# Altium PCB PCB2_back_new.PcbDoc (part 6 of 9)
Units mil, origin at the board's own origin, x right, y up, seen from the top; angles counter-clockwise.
Board outline 6299 x 3937 mil, 4 copper layers (TopLayer, GROUND, VCC, BottomLayer); 253 components, 421 nets, 2085 pads, 712 vias.
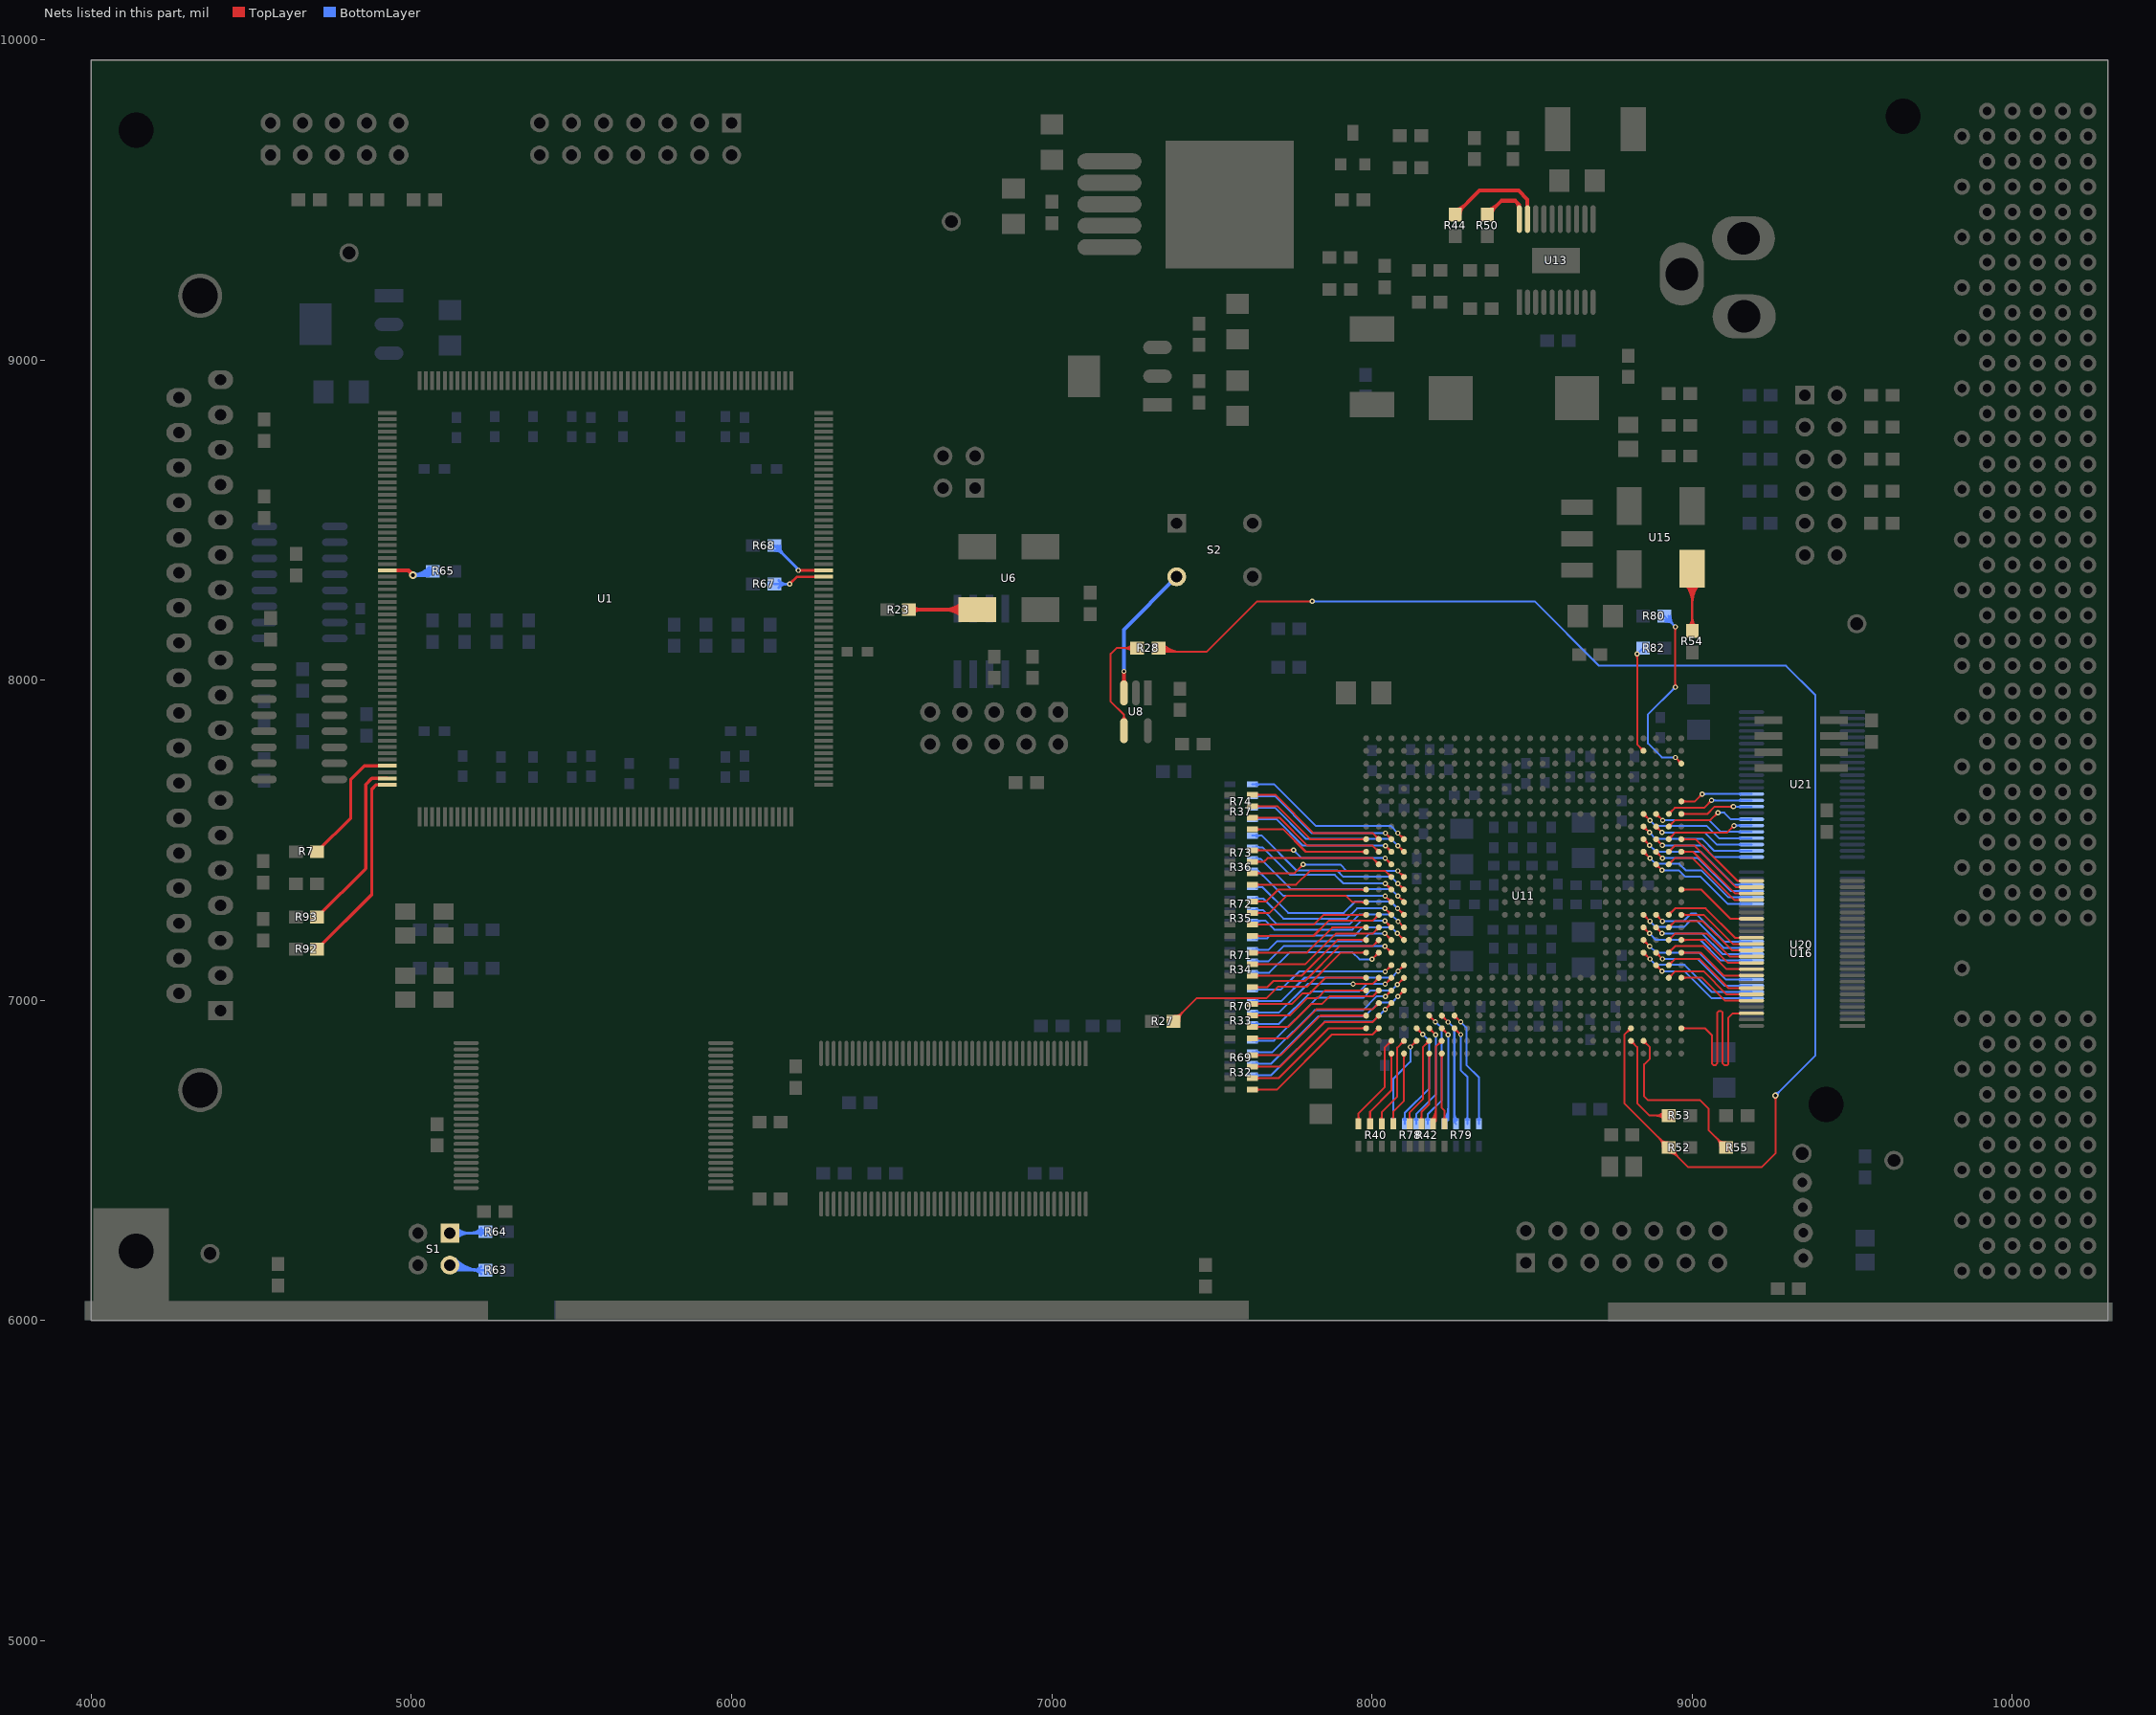
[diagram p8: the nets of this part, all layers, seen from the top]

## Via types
v1: diameter 16, hole 8, TopLayer to BottomLayer, 311 vias
v2: diameter 20, hole 10, TopLayer to BottomLayer, 202 vias
v3: diameter 24, hole 12, TopLayer to BottomLayer, 179 vias
v4: diameter 40, hole 20, TopLayer to BottomLayer, 12 vias
v5: diameter 30, hole 15, TopLayer to BottomLayer, 8 vias

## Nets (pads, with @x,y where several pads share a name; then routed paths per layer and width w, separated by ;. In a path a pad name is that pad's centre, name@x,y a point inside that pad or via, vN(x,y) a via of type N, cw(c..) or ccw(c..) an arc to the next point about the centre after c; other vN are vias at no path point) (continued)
NetR7_2: R7.2 U1.177 | length 401.7
  TopLayer w10: R7.2@4705.46,7464 4810.3,7568.84 4810.3,7690.3 4852.35,7732.35 U1.177@4924.9,7732.35
NetR23_1: R23.1 U6.3 | length 473.2
  TopLayer w12: R23.1@6553.46,8220 U6.3@6767.15,8220 ; R23.1@6565.11,8210.32 cw(c6588.47,8186.96) 6588.47,8220 cw(c6588.47,8253.04) R23.1@6565.11,8229.68 ; U6.3@6723.87,8196.4 ccw(c6666.9,8139.44) 6666.9,8220 ccw(c6666.9,8300.56) U6.3@6723.87,8243.6 ; U6.3@6732.35,8204.89 ccw(c6695.87,8168.41) 6695.87,8220 ccw(c6695.87,8271.59) U6.3@6732.35,8235.11
NetR27_1: R27.1 U11.J26 | length 818.8
  TopLayer w6: R27.1@7379.46,6934 7452.46,7007 7671,7007 7706,7042 7796,7042 7902.96,7148.96 U11.J26@7981.75,7148.96 ; R27.1@7381.43,6944.69 ccw(c7381.43,6965.73) R27.1@7396.31,6950.85 ; R27.1@7381.43,6950.69 ccw(c7381.43,6986.21) 7406.56,6961.09 ; R27.1@7392.12,6934 cw(c7422.67,6934) 7401.07,6955.6 ; R27.1@7398.12,6934 cw(c7443.15,6934) 7411.31,6965.84 ; U11.J26@7977.33,7144.54 ccw(c7966.65,7133.87) 7966.65,7148.96 ccw(c7966.65,7164.05) U11.J26@7977.33,7153.38
NetR28_1: R28.1 U8.4 | length 484.4
  TopLayer w6: U8.4@7218.97,7875.68 ccw(c7203.93,7890.72) 7225.2,7890.72 ccw(c7246.47,7890.72) U8.4@7231.43,7875.68 ; U8.4@7225.2,7841.89 7225.2,7891.8 7184,7933 7184,8082 7202,8100 R28.1@7266.54,8100 ; R28.1@7252.77,8088.2 ccw(c7224.29,8059.72) 7224.29,8100 ccw(c7224.29,8140.28) R28.1@7252.77,8111.8 ; R28.1@7257.01,8092.44 ccw(c7238.77,8074.2) 7238.77,8100 ccw(c7238.77,8125.8) R28.1@7257.01,8107.56
NetR28_2: R28.2 R52.2 U11.C5 | length 5030.8
  TopLayer w6: R28.2@7333.46,8100 7345.46,8088 7483,8088 7641,8246 v1(7813,8246) ; R28.2@7334.5,8099.07 ccw(c7361.23,8125.8) 7361.23,8088 ; R28.2@7338.75,8103.31 ccw(c7375.71,8140.28) 7375.71,8088 ; R28.2@7342.99,8107.56 ccw(c7390.2,8154.77) 7390.2,8088 ; R28.2@7347.23,8111.8 ccw(c7404.68,8169.25) 7404.68,8088 ; U11.C5@8802.27,6912.74 cw(c8787.17,6912.74) 8797.85,6902.07 cw(c8808.52,6891.39) U11.C5@8808.52,6906.49 ; U11.C5@8808.52,6912.74 8788,6892.22 8788,6678.54 8987.54,6479 9217,6479 9260,6522 v2(9260,6703) ; 8894.69,6571.84 cw(c8862.85,6540) R52.2@8907.88,6540 ; 8899.44,6567.09 ccw(c8924.57,6592.21) R52.2@8924.57,6556.69 ; 8904.93,6561.6 cw(c8883.33,6540) R52.2@8913.88,6540 ; R52.2@8909.69,6556.85 ccw(c8924.57,6571.73) R52.2@8924.57,6550.69 ; R52.2@8928.5,6523.31 cw(c8928.5,6487.79) 8953.63,6512.91 ; R52.2@8928.5,6529.31 cw(c8928.5,6508.27) R52.2@8943.38,6523.15 ; R52.2@8939.19,6540 ccw(c8969.74,6540) 8948.14,6518.4 ; R52.2@8945.19,6540 ccw(c8990.22,6540) 8958.38,6508.16 ; v2@9255.05,6698.05 cw(c9243.1,6686.1) 9260,6686.1 cw(c9276.9,6686.1) v2@9264.95,6698.05
  BottomLayer w6: v1(7813,8246) 8508,8246 8709,8045 9293,8045 9384,7954 9384,6827 v2(9260,6703) ; v1@7816.54,8242.46 cw(c7825.07,8233.93) 7825.07,8246 cw(c7825.07,8258.07) v1@7816.54,8249.54 ; v2@9260,6710 ccw(c9260,6726.9) 9271.95,6714.95 ccw(c9283.9,6703) v2@9267,6703
NetR32_1: R32.1 U11.C25 | length 521
  TopLayer w6: R32.1@7626,6721 7703,6721 7875,6893 8001.38,6893 U11.C25@8021.12,6912.74 ; R32.1@7638.74,6716.76 cw(c7648.99,6706.51) 7648.99,6721 cw(c7648.99,6735.49) R32.1@7638.74,6725.24 ; U11.C25@8014.87,6912.74 cw(c7999.77,6912.74) 8010.44,6902.07 cw(c8021.12,6891.39) U11.C25@8021.12,6906.49
NetR32_2: R32.2 U11.C26 | length 470.6
  TopLayer w6: R32.2@7628.74,6759.74 R32.2@7626,6757 7709,6757 7864.74,6912.74 U11.C26@7981.75,6912.74 ; R32.2@7638.74,6752.76 cw(c7648.99,6742.51) 7648.99,6757 cw(c7648.99,6771.49) R32.2@7638.74,6761.24 ; U11.C26@7977.33,6908.32 ccw(c7966.65,6897.65) 7966.65,6912.74 ccw(c7966.65,6927.83) U11.C26@7977.33,6917.16
NetR32_3: R32.3 U11.D25 | length 507.5
  TopLayer w6: R32.3@7626,6793 7713,6793 7852,6932 8001.01,6932 U11.D25@8021.12,6952.11 ; R32.3@7638.74,6788.76 cw(c7648.99,6778.51) 7648.99,6793 cw(c7648.99,6807.49) R32.3@7638.74,6797.24 ; U11.D25@8014.87,6952.11 cw(c7999.77,6952.11) 8010.44,6941.44 cw(c8021.12,6930.77) U11.D25@8021.12,6945.86
NetR32_4: R32.4 U11.D26 | length 453.2
  TopLayer w6: R32.4@7626,6829 7716,6829 7839.11,6952.11 U11.D26@7981.75,6952.11 ; R32.4@7638.74,6824.76 cw(c7648.99,6814.51) 7648.99,6829 cw(c7648.99,6843.49) R32.4@7638.74,6833.24 ; U11.D26@7977.33,6947.69 ccw(c7966.65,6937.02) 7966.65,6952.11 ccw(c7966.65,6967.2) U11.D26@7977.33,6956.53
NetR33_1: R33.1 U11.E25 | length 487.3
  TopLayer w6: R33.1@7626,6881 7735,6881 7826,6972 8001.64,6972 U11.E25@8021.12,6991.48 ; R33.1@7638.74,6876.76 cw(c7648.99,6866.51) 7648.99,6881 cw(c7648.99,6895.49) R33.1@7638.74,6885.24 ; U11.E25@8014.87,6991.48 cw(c7999.77,6991.48) 8010.44,6980.81 cw(c8021.12,6970.14) U11.E25@8021.12,6985.23
NetR33_2: R33.2 U11.F25 | length 488.7
  TopLayer w6: R33.2@7626,6917 7739,6917 7811,6989 7844,6989 7867,7012 8002.27,7012 U11.F25@8021.12,7030.85 ; R33.2@7638.74,6912.76 cw(c7648.99,6902.51) 7648.99,6917 cw(c7648.99,6931.49) R33.2@7638.74,6921.24 ; U11.F25@8014.87,7030.85 cw(c7999.77,7030.85) 8010.44,7020.18 cw(c8021.12,7009.51) U11.F25@8021.12,7024.6
NetR33_3: R33.3 U11.F26 | length 434.5
  TopLayer w6: R33.3@7626,6953 7744.15,6953 7797.15,7006 7829,7006 7853.85,7030.85 U11.F26@7981.75,7030.85 ; R33.3@7638.74,6948.76 cw(c7648.99,6938.51) 7648.99,6953 cw(c7648.99,6967.49) R33.3@7638.74,6957.24 ; U11.F26@7977.33,7026.43 ccw(c7966.65,7015.76) 7966.65,7030.85 ccw(c7966.65,7045.94) U11.F26@7977.33,7035.27
NetR33_4: R33.4 U11.G26 | length 435.9
  TopLayer w6: R33.4@7626,6989 7750,6989 7782,7021 7805,7021 7854.22,7070.22 U11.G26@7981.75,7070.22 ; R33.4@7638.74,6984.76 cw(c7648.99,6974.51) 7648.99,6989 cw(c7648.99,7003.49) R33.4@7638.74,6993.24 ; U11.G26@7977.33,7065.8 ccw(c7966.65,7055.13) 7966.65,7070.22 ccw(c7966.65,7085.31) U11.G26@7977.33,7074.64
NetR34_1: R34.1 U11.K25 | length 502.6
  TopLayer w6: R34.1@7626,7041 7673,7041 7692.45,7060.45 7790.45,7060.45 7899,7169 8001.79,7169 U11.K25@8021.12,7188.33 ; R34.1@7638.74,7036.76 cw(c7648.99,7026.51) 7648.99,7041 cw(c7648.99,7055.49) R34.1@7638.74,7045.24 ; U11.K25@8014.87,7188.33 cw(c7999.77,7188.33) 8010.44,7177.66 cw(c8021.12,7166.99) U11.K25@8021.12,7182.08
NetR34_2: R34.2 U11.K26 | length 448.3
  TopLayer w6: R34.2@7626,7077 7781,7077 7892.33,7188.33 U11.K26@7981.75,7188.33 ; R34.2@7638.74,7072.76 cw(c7648.99,7062.51) 7648.99,7077 cw(c7648.99,7091.49) R34.2@7638.74,7081.24 ; U11.K26@7977.33,7183.91 ccw(c7966.65,7173.24) 7966.65,7188.33 ccw(c7966.65,7203.42) U11.K26@7977.33,7192.75
NetR34_3: R34.3 U11.L25 | length 489.1
  TopLayer w6: R34.3@7626,7113 7792,7113 7887,7208 8001.42,7208 U11.L25@8021.12,7227.7 ; R34.3@7638.74,7108.76 cw(c7648.99,7098.51) 7648.99,7113 cw(c7648.99,7127.49) R34.3@7638.74,7117.24 ; U11.L25@8014.87,7227.7 cw(c7999.77,7227.7) 8010.44,7217.03 cw(c8021.12,7206.36) U11.L25@8021.12,7221.45
NetR34_4: R34.4 U11.L26 | length 434.8
  TopLayer w6: R34.4@7626,7149 7797,7149 7875.7,7227.7 U11.L26@7981.75,7227.7 ; R34.4@7638.74,7144.76 cw(c7648.99,7134.51) 7648.99,7149 cw(c7648.99,7163.49) R34.4@7638.74,7153.24 ; U11.L26@7977.33,7223.28 ccw(c7966.65,7212.61) 7966.65,7227.7 ccw(c7966.65,7242.79) U11.L26@7977.33,7232.12
NetR35_1: R35.1 U11.M25 | length 468.9
  TopLayer w6: R35.1@7626,7201 7817,7201 7864,7248 8002.05,7248 U11.M25@8021.12,7267.07 ; R35.1@7638.74,7196.76 cw(c7648.99,7186.51) 7648.99,7201 cw(c7648.99,7215.49) R35.1@7638.74,7205.24 ; U11.M25@8014.87,7267.07 cw(c7999.77,7267.07) 8010.44,7256.4 cw(c8021.12,7245.73) U11.M25@8021.12,7260.82
NetR35_2: R35.2 U11.M26 | length 414.7
  TopLayer w6: R35.2@7626,7237 7819,7237 7849.07,7267.07 U11.M26@7981.75,7267.07 ; R35.2@7638.74,7232.76 cw(c7648.99,7222.51) 7648.99,7237 cw(c7648.99,7251.49) R35.2@7638.74,7241.24 ; U11.M26@7977.33,7262.65 ccw(c7966.65,7251.98) 7966.65,7267.07 ccw(c7966.65,7282.16) U11.M26@7977.33,7271.49
NetR35_3: R35.3 U11.N26 | length 432.3
  TopLayer w6: R35.3@7626,7273 7680,7273 7733,7326 7919,7326 7938.56,7306.44 U11.N26@7981.75,7306.44 ; R35.3@7638.74,7268.76 cw(c7648.99,7258.51) 7648.99,7273 cw(c7648.99,7287.49) R35.3@7638.74,7277.24 ; U11.N26@7977.33,7302.02 ccw(c7966.65,7291.35) 7966.65,7306.44 ccw(c7966.65,7321.53) U11.N26@7977.33,7310.86
NetR35_4: R35.4 U11.P26 | length 417.5
  TopLayer w6: R35.4@7626,7309 7670,7309 7706.81,7345.81 U11.P26@7981.75,7345.81 ; R35.4@7638.74,7304.76 cw(c7648.99,7294.51) 7648.99,7309 cw(c7648.99,7323.49) R35.4@7638.74,7313.24 ; U11.P26@7977.33,7341.39 ccw(c7966.65,7330.72) 7966.65,7345.81 ccw(c7966.65,7360.9) U11.P26@7977.33,7350.23
NetR36_1: R36.1 U11.R24 | length 506.6
  TopLayer w6: R36.1@7626,7361 7763,7361 7806,7404 8041.67,7404 U11.R24@8060.49,7385.18 ; R36.1@7638.74,7356.76 cw(c7648.99,7346.51) 7648.99,7361 cw(c7648.99,7375.49) R36.1@7638.74,7365.24 ; U11.R24@8054.24,7385.18 ccw(c8039.14,7385.18) 8049.82,7395.85 ccw(c8060.49,7406.53) U11.R24@8060.49,7391.43
NetR36_2: R36.2 U11.R23 | length 585.5
  TopLayer w6: R36.2@7626,7397 7758,7397 v1(7785,7424) ; R36.2@7638.74,7392.76 cw(c7648.99,7382.51) 7648.99,7397 cw(c7648.99,7411.49) R36.2@7638.74,7401.24 ; v1@7780,7424 cw(c7767.93,7424) 7776.46,7415.46 cw(c7785,7406.93) v1@7785,7419 ; v1(8081.04,7404) U11.R23@8099.86,7385.18 ; U11.R23@8093.61,7385.18 ccw(c8078.51,7385.18) 8089.19,7395.85 ccw(c8099.86,7406.53) U11.R23@8099.86,7391.43
  BottomLayer w6: v1(7785,7424) 7901,7424 7921,7404 v1(8081.04,7404) ; v1@7788.54,7420.46 cw(c7797.07,7411.93) 7797.07,7424 cw(c7797.07,7436.07) v1@7788.54,7427.54
NetR36_3: R36.3 U11.T25 | length 454.2
  TopLayer w6: R36.3@7626,7433 7663,7433 7674,7444 8001.67,7444 U11.T25@8021.12,7424.55 ; R36.3@7638.74,7428.76 cw(c7648.99,7418.51) 7648.99,7433 cw(c7648.99,7447.49) R36.3@7638.74,7437.24 ; U11.T25@8014.87,7424.55 ccw(c7999.77,7424.55) 8010.44,7435.22 ccw(c8021.12,7445.9) U11.T25@8021.12,7430.8
NetR36_4: R36.4 U11.T24 | length 537.3
  TopLayer w6: R36.4@7626,7469 v1(7755,7469) ; R36.4@7638.74,7464.76 cw(c7648.99,7454.51) 7648.99,7469 cw(c7648.99,7483.49) R36.4@7638.74,7473.24 ; v1@7751.46,7465.46 ccw(c7742.93,7456.93) 7742.93,7469 ccw(c7742.93,7481.07) v1@7751.46,7472.54 ; v1(8041.04,7444) U11.T24@8060.49,7424.55 ; U11.T24@8054.24,7424.55 ccw(c8039.14,7424.55) 8049.82,7435.22 ccw(c8060.49,7445.9) U11.T24@8060.49,7430.8
  BottomLayer w6: v1@7755,7464 cw(c7755,7451.93) 7763.54,7460.46 cw(c7772.07,7469) v1@7760,7469 ; v1(7755,7469) 7780,7444 v1(8041.04,7444)
NetR37_1: R37.1 U11.U26 | length 431.2
  TopLayer w6: R37.1@7626,7534 7723,7534 7793.08,7463.92 U11.U26@7981.75,7463.92 ; R37.1@7638.74,7529.76 cw(c7648.99,7519.51) 7648.99,7534 cw(c7648.99,7548.49) R37.1@7638.74,7538.24 ; U11.U26@7977.33,7459.5 ccw(c7966.65,7448.83) 7966.65,7463.92 ccw(c7966.65,7479.02) U11.U26@7977.33,7468.34
NetR37_2: R37.2 U11.U25 | length 485.5
  TopLayer w6: R37.2@7626,7570 7711,7570 7798,7483 8002.04,7483 U11.U25@8021.12,7463.92 ; R37.2@7638.74,7565.76 cw(c7648.99,7555.51) 7648.99,7570 cw(c7648.99,7584.49) R37.2@7638.74,7574.24 ; U11.U25@8014.87,7463.92 ccw(c7999.77,7463.92) 8010.44,7474.59 ccw(c8021.12,7485.27) U11.U25@8021.12,7470.17
NetR37_3: R37.3 U11.V26 | length 444.8
  TopLayer w6: R37.3@7626,7606 7704,7606 7806.71,7503.29 U11.V26@7981.75,7503.29 ; R37.3@7638.74,7601.76 cw(c7648.99,7591.51) 7648.99,7606 cw(c7648.99,7620.49) R37.3@7638.74,7610.24 ; U11.V26@7977.33,7498.87 ccw(c7966.65,7488.2) 7966.65,7503.29 ccw(c7966.65,7518.39) U11.V26@7977.33,7507.71
NetR37_4: R37.4 U11.V25 | length 499
  TopLayer w6: R37.4@7626,7642 7698,7642 7818,7522 8002.41,7522 U11.V25@8021.12,7503.29 ; R37.4@7638.74,7637.76 cw(c7648.99,7627.51) 7648.99,7642 cw(c7648.99,7656.49) R37.4@7638.74,7646.24 ; U11.V25@8014.87,7503.29 ccw(c7999.77,7503.29) 8010.44,7513.96 ccw(c8021.12,7524.64) U11.V25@8021.12,7509.54
NetR40_1: R40.1 U11.A23 | length 280.5
  TopLayer w6: R40.1@8061.76,6626.74 ccw(c8051.51,6636.99) 8066,6636.99 ccw(c8080.49,6636.99) R40.1@8070.24,6626.74 ; R40.1@8066,6614 8066,6652 8099.86,6685.86 U11.A23@8099.86,6834 ; U11.A23@8095.44,6829.58 cw(c8084.76,6818.91) 8099.86,6818.91 cw(c8114.95,6818.91) U11.A23@8104.28,6829.58
NetR40_2: R40.2 U11.B23 | length 334.8
  TopLayer w6: R40.2@8025.76,6626.74 ccw(c8015.51,6636.99) 8030,6636.99 ccw(c8044.49,6636.99) R40.2@8034.24,6626.74 ; R40.2@8030,6614 8030,6650 8079,6699 8079,6852.51 U11.B23@8099.86,6873.37 ; U11.B23@8093.61,6873.37 cw(c8078.51,6873.37) 8089.19,6862.7 cw(c8099.86,6852.02) U11.B23@8099.86,6867.12
NetR40_3: R40.3 U11.A24 | length 294
  TopLayer w6: R40.3@7989.76,6626.74 ccw(c7979.51,6636.99) 7994,6636.99 ccw(c8008.49,6636.99) R40.3@7998.24,6626.74 ; R40.3@7994,6614 7994,6652 8060.49,6718.49 U11.A24@8060.49,6834 ; U11.A24@8056.07,6829.58 cw(c8045.39,6818.91) 8060.49,6818.91 cw(c8075.58,6818.91) U11.A24@8064.91,6829.58
NetR40_4: R40.4 U11.B24 | length 348.3
  TopLayer w6: R40.4@7953.76,6626.74 ccw(c7943.51,6636.99) 7958,6636.99 ccw(c7972.49,6636.99) R40.4@7962.24,6626.74 ; R40.4@7958,6614 7958,6647 8040,6729 8040,6852.88 U11.B24@8060.49,6873.37 ; U11.B24@8054.24,6873.37 cw(c8039.14,6873.37) 8049.82,6862.7 cw(c8060.49,6852.02) U11.B24@8060.49,6867.12
NetR42_1: R42.1 U11.A20 | length 269.8
  TopLayer w6: U11.A20@8213.55,6829.58 cw(c8202.87,6818.91) 8217.97,6818.91 cw(c8233.06,6818.91) U11.A20@8222.39,6829.58 ; U11.A20@8217.97,6834 8217.97,6664.03 8226,6656 R42.1@8226,6614 ; R42.1@8221.76,6626.74 ccw(c8211.51,6636.99) 8226,6636.99 ccw(c8240.49,6636.99) R42.1@8230.24,6626.74
NetR42_2: R42.2 U11.B20 | length 367.1
  TopLayer w6: R42.2@8185.76,6626.74 ccw(c8153.79,6658.71) 8199,6658.71 ; R42.2@8190,6614 8199,6623 8199,6854.4 U11.B20@8217.97,6873.37 ; R42.2@8190,6622.5 ccw(c8168.27,6644.23) 8199,6644.23 ; R42.2@8194.24,6618.26 ccw(c8182.76,6629.74) 8199,6629.74 ; U11.B20@8211.72,6873.37 cw(c8196.62,6873.37) 8207.3,6862.7 cw(c8217.97,6852.02) U11.B20@8217.97,6867.12
NetR42_3: R42.3 U11.A21 | length 276.7
  TopLayer w6: R42.3@8149.76,6626.74 ccw(c8139.51,6636.99) 8154,6636.99 ccw(c8168.49,6636.99) R42.3@8158.24,6626.74 ; R42.3@8154,6614 8154,6651 8178.6,6675.6 U11.A21@8178.6,6834 ; U11.A21@8174.18,6829.58 cw(c8163.5,6818.91) 8178.6,6818.91 cw(c8193.69,6818.91) U11.A21@8183.02,6829.58
NetR42_4: R42.4 U11.B21 | length 330.9
  TopLayer w6: R42.4@8113.76,6626.74 ccw(c8103.51,6636.99) 8118,6636.99 ccw(c8132.49,6636.99) R42.4@8122.24,6626.74 ; R42.4@8118,6614 8118,6650 8159,6691 8159,6853.77 U11.B21@8178.6,6873.37 ; U11.B21@8172.35,6873.37 cw(c8157.25,6873.37) 8167.93,6862.7 cw(c8178.6,6852.02) U11.B21@8178.6,6867.12
NetR44_1: R44.1 U13.19 | length 381.8
  TopLayer w12: R44.1@8260,9453.46 8335.54,9529 8458,9529 8485.59,9501.41 U13.19@8485.59,9439.84 ; R44.1@8260,9469.12 ccw(c8260,9506.91) 8286.72,9480.19 ; R44.1@8273.69,9455.43 cw(c8301.97,9455.43) 8281.97,9475.43
NetR50_2: R50.2 U13.20 | length 239.6
  TopLayer w12: R50.2@8360,9453.46 8403.54,9497 8447,9497 8460,9484 U13.20@8460,9439.84 ; R50.2@8360,9469.12 ccw(c8360,9506.91) 8386.72,9480.19 ; R50.2@8373.69,9455.43 cw(c8401.97,9455.43) 8381.97,9475.43 ; 8450.63,9493.37 cw(c8432.54,9475.28) U13.20@8458.13,9475.28
NetR53_2: R53.2 U11.B5 | length 448.1
  TopLayer w6: U11.B5@8808.52,6867.12 cw(c8808.52,6852.02) 8819.19,6862.7 cw(c8829.86,6873.37) U11.B5@8814.77,6873.37 ; U11.B5@8808.52,6873.37 8828,6853.89 8828,6679 8867,6640 R53.2@8926.54,6640 R53.2@8926.54,6643.46 ; R53.2@8912.77,6628.2 ccw(c8884.29,6599.72) 8884.29,6640 ccw(c8884.29,6680.28) R53.2@8912.77,6651.8 ; R53.2@8917.01,6632.44 ccw(c8898.77,6614.2) 8898.77,6640 ccw(c8898.77,6665.8) R53.2@8917.01,6647.56
NetR54_1: R54.1 U15.3 | length 584.5
  TopLayer w8: U15.3@8974.99,8302.45 cw(c8914.61,8242.07) 9000,8242.07 cw(c9085.39,8242.07) U15.3@9025.01,8302.45 ; U15.3@8980.65,8308.11 cw(c8933.92,8261.39) 9000,8261.39 cw(c9066.08,8261.39) U15.3@9019.35,8308.11 ; U15.3@8986.3,8313.77 cw(c8953.24,8280.7) 9000,8280.7 cw(c9046.76,8280.7) U15.3@9013.7,8313.77 ; R54.1@8988.91,8166.52 ccw(c8962.13,8193.3) 9000,8193.3 ccw(c9037.87,8193.3) R54.1@9011.09,8166.52 ; R54.1@9000,8153.46 U15.3@9000,8367.15
NetR55_2: R55.2 U11.B4 | length 678.4
  TopLayer w6: U11.B4@8847.89,6867.12 cw(c8847.89,6852.02) 8858.56,6862.7 cw(c8869.24,6873.37) U11.B4@8854.14,6873.37 ; U11.B4@8847.89,6873.37 8868,6853.26 8868,6818 8850,6800 8850,6700 8862,6688 9025,6688 9051,6662 9051,6595.54 R55.2@9106.54,6540 ; 9074.69,6571.84 cw(c9042.85,6540) R55.2@9087.88,6540 ; 9079.44,6567.09 ccw(c9104.57,6592.21) R55.2@9104.57,6556.69 ; 9084.93,6561.6 cw(c9063.33,6540) R55.2@9093.88,6540 ; R55.2@9089.69,6556.85 ccw(c9104.57,6571.73) R55.2@9104.57,6550.69
NetR63_2: R63.2 S1.2 | length 452.9
  BottomLayer w8: S1.2@5118,6173 5134,6157 R63.2@5230.54,6157 ; S1.2@5121.08,6174.08 ccw(c5162.32,6215.32) 5162.32,6157 ; S1.2@5126.74,6179.74 ccw(c5181.63,6234.63) 5181.63,6157 ; S1.2@5132.39,6185.39 ccw(c5200.94,6253.94) 5200.94,6157 ; S1.2@5138.05,6191.05 ccw(c5220.26,6273.26) R63.2@5220.26,6157 ; R63.2@5217.48,6145.91 ccw(c5190.7,6119.13) 5190.7,6157 ccw(c5190.7,6194.87) R63.2@5217.48,6168.09
NetR64_2: R64.2 S1.1 | length 362.2
  BottomLayer w8: S1.1@5118,6273 5226.54,6273 R64.2@5230.54,6277 ; S1.1@5132.39,6260.61 cw(c5162.32,6230.68) 5162.32,6273 cw(c5162.32,6315.32) S1.1@5132.39,6285.39 ; S1.1@5138.05,6254.95 cw(c5181.63,6211.37) 5181.63,6273 cw(c5181.63,6334.63) S1.1@5138.05,6291.05 ; 5181.04,6273 ccw(c5181.04,6324.52) R64.2@5217.48,6288.09 ; R64.2@5217.48,6265.91 ccw(c5200.36,6248.79) 5200.36,6273 ccw(c5200.36,6305.21) R64.2@5223.13,6282.43
NetR67_2: R67.2 U1.34 | length 240.1
  TopLayer w8: v1(6181,8300) 6203.9,8322.9 U1.34@6274.31,8322.9 ; v1@6181,8304 ccw(c6181,8313.66) 6187.83,8306.83 ccw(c6194.66,8300) v1@6185,8300
  BottomLayer w8: R67.2@6133.46,8300 v1(6181,8300) ; R67.2@6146.52,8288.91 cw(c6173.3,8262.13) 6173.3,8300 cw(c6173.3,8337.87) R67.2@6146.52,8311.09 ; v1@6178.17,8297.17 ccw(c6171.34,8290.34) 6171.34,8300 ccw(c6171.34,8309.66) v1@6178.17,8302.83
NetR68_2: R68.2 U1.35 | length 282.8
  TopLayer w8: v1(6208.58,8342.58) U1.35@6274.31,8342.58 ; v1@6211.41,8339.75 cw(c6218.24,8332.93) 6218.24,8342.58 cw(c6218.24,8352.24) v1@6211.41,8345.41
  BottomLayer w8: R68.2@6133.46,8420 6208.58,8344.88 v1(6208.58,8342.58) v1@6206,8340 ; R68.2@6135.43,8404.32 cw(c6135.43,8371.2) 6158.85,8394.62 ; R68.2@6143.12,8420 ccw(c6166.42,8420) R68.2@6149.94,8403.52 ; R68.2@6151.12,8420 ccw(c6193.74,8420) 6163.6,8389.86 ; 6200.13,8353.34 cw(c6189.37,8342.58) v1@6204.58,8342.58
NetR69_1: R69.1 U11.G23 | length 601.8
  TopLayer w6: v1(8079,7049) 8099.86,7069.86 U11.G23@8099.86,7070.22 ; 8088.93,7058.93 ccw(c8077.64,7070.22) U11.G23@8093.61,7070.22 ; 8089.8,7059.8 cw(c8099.86,7049.75) U11.G23@8099.86,7063.97
  BottomLayer w6: R69.1@7626,6874 7694,6874 7828,7008 7973,7008 7996,7031 8061,7031 v1(8079,7049) ; R69.1@7638.74,6869.76 cw(c7648.99,6859.51) 7648.99,6874 cw(c7648.99,6888.49) R69.1@7638.74,6878.24
NetR69_2: R69.2 U11.F24 | length 560.8
  TopLayer w6: v1(8041.64,7012) U11.F24@8060.49,7030.85 ; U11.F24@8054.24,7030.85 cw(c8039.14,7030.85) 8049.82,7020.18 cw(c8060.49,7009.51) U11.F24@8060.49,7024.6
  BottomLayer w6: R69.2@7626,6838 7689,6838 7820,6969 7971,6969 8014,7012 v1(8041.64,7012) ; R69.2@7638.74,6833.76 cw(c7648.99,6823.51) 7648.99,6838 cw(c7648.99,6852.49) R69.2@7638.74,6842.24
NetR69_3: R69.3 U11.F23 | length 615.1
  TopLayer w6: v1(8081.01,7012) U11.F23@8099.86,7030.85 ; U11.F23@8093.61,7030.85 cw(c8078.51,7030.85) 8089.19,7020.18 cw(c8099.86,7009.51) U11.F23@8099.86,7024.6
  BottomLayer w6: R69.3@7626,6802 7685,6802 7833,6950 7978,6950 8021,6993 8062.01,6993 v1(8081.01,7012) ; R69.3@7638.74,6797.76 cw(c7648.99,6787.51) 7648.99,6802 cw(c7648.99,6816.49) R69.3@7638.74,6806.24
NetR69_4: R69.4 U11.E24 | length 574.3
  TopLayer w6: v1(8041.01,6972) U11.E24@8060.49,6991.48 ; U11.E24@8054.24,6991.48 cw(c8039.14,6991.48) 8049.82,6980.81 cw(c8060.49,6970.14) U11.E24@8060.49,6985.23
  BottomLayer w6: R69.4@7626,6766 7685,6766 7852,6933 8002.01,6933 v1(8041.01,6972) ; R69.4@7638.74,6761.76 cw(c7648.99,6751.51) 7648.99,6766 cw(c7648.99,6780.49) R69.4@7638.74,6770.24
NetR70_1: R70.1 U11.H24 | length 512.3
  TopLayer w6: v1(8040.9,7090) U11.H24@8060.49,7109.59 ; U11.H24@8054.24,7109.59 cw(c8039.14,7109.59) 8049.82,7098.92 cw(c8060.49,7088.25) U11.H24@8060.49,7103.34
  BottomLayer w6: R70.1@7626,7034 7716,7034 7772,7090 v1(8040.9,7090) ; R70.1@7638.74,7029.76 cw(c7648.99,7019.51) 7648.99,7034 cw(c7648.99,7048.49) R70.1@7638.74,7038.24
NetR70_2: R70.2 U11.H23 | length 566.5
  TopLayer w6: v1(8081.27,7091) U11.H23@8099.86,7109.59 ; U11.H23@8093.61,7109.59 cw(c8078.51,7109.59) 8089.19,7098.92 cw(c8099.86,7088.25) U11.H23@8099.86,7103.34
  BottomLayer w6: R70.2@7626,6998 7717,6998 7790,7071 8061.27,7071 v1(8081.27,7091) ; R70.2@7638.74,6993.76 cw(c7648.99,6983.51) 7648.99,6998 cw(c7648.99,7012.49) R70.2@7638.74,7002.24
NetR70_3: R70.3 U11.G25 | length 486.4
  TopLayer w6: v1(7941,7051) 8001.9,7051 U11.G25@8021.12,7070.22 ; U11.G25@8014.87,7070.22 cw(c7999.77,7070.22) 8010.44,7059.55 cw(c8021.12,7048.88) U11.G25@8021.12,7063.97
  BottomLayer w6: R70.3@7626,6962 7710,6962 7799,7051 v1(7941,7051) ; R70.3@7638.74,6957.76 cw(c7648.99,6947.51) 7648.99,6962 cw(c7648.99,6976.49) R70.3@7638.74,6966.24
NetR70_4: R70.4 U11.G24 | length 540.7
  TopLayer w6: v1(8041.27,7051) U11.G24@8060.49,7070.22 ; U11.G24@8054.24,7070.22 cw(c8039.14,7070.22) 8049.82,7059.55 cw(c8060.49,7048.88) U11.G24@8060.49,7063.97
  BottomLayer w6: R70.4@7626,6926 7709,6926 7810,7027 7960,7027 7984,7051 v1(8041.27,7051) ; R70.4@7638.74,6921.76 cw(c7648.99,6911.51) 7648.99,6926 cw(c7648.99,6940.49) R70.4@7638.74,6930.24
NetR71_1: R71.1 U11.K23 | length 550.8
  TopLayer w6: v1(8079.19,7209) U11.K23@8099.86,7188.33 ; U11.K23@8093.61,7188.33 ccw(c8078.51,7188.33) 8089.19,7199 ccw(c8099.86,7209.68) U11.K23@8099.86,7194.58
  BottomLayer w6: R71.1@7626,7194 7673,7194 7682,7203 7947,7203 7972,7228 8060.19,7228 v1(8079.19,7209) ; R71.1@7638.74,7189.76 cw(c7648.99,7179.51) 7648.99,7194 cw(c7648.99,7208.49) R71.1@7638.74,7198.24
NetR71_2: R71.2 U11.K24 | length 510.6
  TopLayer w6: v1(8039.82,7209) U11.K24@8060.49,7188.33 ; U11.K24@8054.24,7188.33 ccw(c8039.14,7188.33) 8049.82,7199 ccw(c8060.49,7209.68) U11.K24@8060.49,7194.58
  BottomLayer w6: R71.2@7626,7158 7677,7158 7704,7185 7968,7185 7992,7209 v1(8039.82,7209) ; R71.2@7638.74,7153.76 cw(c7648.99,7143.51) 7648.99,7158 cw(c7648.99,7172.49) R71.2@7638.74,7162.24
NetR71_3: R71.3 U11.J24 | length 508.7
  TopLayer w6: v1(8040.45,7169) U11.J24@8060.49,7148.96 ; U11.J24@8054.24,7148.96 ccw(c8039.14,7148.96) 8049.82,7159.63 ccw(c8060.49,7170.31) U11.J24@8060.49,7155.21
  BottomLayer w6: R71.3@7626,7122 7677,7122 7724,7169 v1(8040.45,7169) ; R71.3@7638.74,7117.76 cw(c7648.99,7107.51) 7648.99,7122 cw(c7648.99,7136.49) R71.3@7638.74,7126.24
NetR71_4: R71.4 U11.J25 | length 485.9
  TopLayer w6: v1(8000.16,7128) U11.J25@8021.12,7148.96 ; U11.J25@8014.87,7148.96 cw(c7999.77,7148.96) 8010.44,7138.29 cw(c8021.12,7127.62) U11.J25@8021.12,7142.71
  BottomLayer w6: R71.4@7626,7086 7679,7086 7743,7150 7939,7150 7961,7128 v1(8000.16,7128) ; R71.4@7638.74,7081.76 cw(c7648.99,7071.51) 7648.99,7086 cw(c7648.99,7100.49) R71.4@7638.74,7090.24
NetR72_1: R72.1 U11.M23 | length 577.5
  TopLayer w6: v1(8079.93,7287) U11.M23@8099.86,7267.07 ; U11.M23@8093.61,7267.07 ccw(c8078.51,7267.07) 8089.19,7277.74 ccw(c8099.86,7288.42) U11.M23@8099.86,7273.32
  BottomLayer w6: R72.1@7638.74,7349.76 cw(c7648.99,7339.51) 7648.99,7354 cw(c7648.99,7368.49) R72.1@7638.74,7358.24 ; R72.1@7639.92,7351.42 cw(c7644,7349.48) 7644,7354 ; R72.1@7639.92,7356.58 ccw(c7644,7358.52) 7644,7354 ; v1(8079.93,7287) 8058.93,7308 7947,7308 7912,7273 7738,7273 7657,7354 7644,7354
NetR72_2: R72.2 U11.M24 | length 528.6
  TopLayer w6: v1(8040.56,7287) U11.M24@8060.49,7267.07 ; U11.M24@8054.24,7267.07 ccw(c8039.14,7267.07) 8049.82,7277.74 ccw(c8060.49,7288.42) U11.M24@8060.49,7273.32
  BottomLayer w6: R72.2@7626,7318 7660,7318 7723,7255 7921,7255 7953,7287 v1(8040.56,7287) ; R72.2@7638.74,7313.76 cw(c7648.99,7303.51) 7648.99,7318 cw(c7648.99,7332.49) R72.2@7638.74,7322.24
NetR72_3: R72.3 U11.L23 | length 544
  TopLayer w6: v1(8081.56,7246) U11.L23@8099.86,7227.7
  BottomLayer w6: R72.3@7626,7282 7659,7282 7703,7238 7930,7238 7960,7268 8059.56,7268 v1(8081.56,7246) ; R72.3@7638.74,7277.76 cw(c7648.99,7267.51) 7648.99,7282 cw(c7648.99,7296.49) R72.3@7638.74,7286.24
NetR72_4: R72.4 U11.L24 | length 512.6
  TopLayer w6: v1(8040.19,7248) U11.L24@8060.49,7227.7 ; U11.L24@8054.24,7227.7 ccw(c8039.14,7227.7) 8049.82,7238.37 ccw(c8060.49,7249.05) U11.L24@8060.49,7233.95
  BottomLayer w6: R72.4@7626,7246 7628,7248 7668,7248 7695,7221 7939,7221 7966,7248 v1(8040.19,7248) ; R72.4@7638.74,7241.76 cw(c7653.81,7226.69) 7653.81,7248 ; R72.4@7638.74,7250.24 ccw(c7644.16,7255.66) 7644.16,7248
NetR73_1: R73.1 U11.P23 | length 590
  TopLayer w6: v1(8080.67,7365) U11.P23@8099.86,7345.81 ; U11.P23@8093.61,7345.81 ccw(c8078.51,7345.81) 8089.19,7356.48 ccw(c8099.86,7367.16) U11.P23@8099.86,7352.06
  BottomLayer w6: R73.1@7626,7514 7656,7514 7764.29,7405.71 7890.29,7405.71 7910,7386 8059.67,7386 v1(8080.67,7365) ; R73.1@7638.74,7509.76 cw(c7648.99,7499.51) 7648.99,7514 cw(c7648.99,7528.49) R73.1@7638.74,7518.24
NetR73_2: R73.2 U11.P24 | length 535.7
  TopLayer w6: v1(8041.3,7365) U11.P24@8060.49,7345.81 ; U11.P24@8054.24,7345.81 ccw(c8039.14,7345.81) 8049.82,7356.48 ccw(c8060.49,7367.16) U11.P24@8060.49,7352.06
  BottomLayer w6: R73.2@7626,7478 7658,7478 7743.96,7392.04 7883.96,7392.04 7911,7365 v1(8041.3,7365) ; R73.2@7638.74,7473.76 cw(c7648.99,7463.51) 7648.99,7478 cw(c7648.99,7492.49) R73.2@7638.74,7482.24
NetR73_3: R73.3 U11.N23 | length 563.7
  TopLayer w6: v1(8081,7326) 8099.86,7307.14 U11.N23@8099.86,7306.44 ; 8090.38,7316.62 ccw(c8099.86,7326.09) U11.N23@8099.86,7312.69
  BottomLayer w6: R73.3@7626,7442 7652,7442 7747,7347 8060,7347 v1(8081,7326) ; R73.3@7638.74,7437.76 cw(c7648.99,7427.51) 7648.99,7442 cw(c7648.99,7456.49) R73.3@7638.74,7446.24
NetR73_4: R73.4 U11.N24 | length 543
  TopLayer w6: v1(8040.93,7326) U11.N24@8060.49,7306.44 ; U11.N24@8054.24,7306.44 ccw(c8039.14,7306.44) 8049.82,7317.11 ccw(c8060.49,7327.79) U11.N24@8060.49,7312.69
  BottomLayer w6: R73.4@7626,7406 7643,7406 7723,7326 v1(8040.93,7326) ; R73.4@7634.5,7400 cw(c7634.5,7364.99) 7659.25,7389.75 ; R73.4@7634.5,7406 cw(c7634.5,7385.48) 7649.01,7399.99
NetR74_1: R74.1 U11.V23 | length 591
  TopLayer w6: v1(8081.15,7522) U11.V23@8099.86,7503.29 ; U11.V23@8093.61,7503.29 ccw(c8078.51,7503.29) 8089.19,7513.96 ccw(c8099.86,7524.64) U11.V23@8099.86,7509.54
  BottomLayer w6: R74.1@7626,7674 7695,7674 7825,7544 8059.15,7544 v1(8081.15,7522) ; R74.1@7638.74,7669.76 cw(c7648.99,7659.51) 7648.99,7674 cw(c7648.99,7688.49) R74.1@7638.74,7678.24
NetR74_2: R74.2 U11.V24 | length 519.7
  TopLayer w6: v1(8041.78,7522) U11.V24@8060.49,7503.29 ; U11.V24@8054.24,7503.29 ccw(c8039.14,7503.29) 8049.82,7513.96 ccw(c8060.49,7524.64) U11.V24@8060.49,7509.54
  BottomLayer w6: R74.2@7638.74,7633.76 cw(c7648.99,7623.51) 7648.99,7638 cw(c7648.99,7652.49) R74.2@7638.74,7642.24 ; R74.2@7643,7638 7696,7638 7812,7522 v1(8041.78,7522)
NetR74_3: R74.3 U11.U23 | length 577.5
  TopLayer w6: v1(8080.78,7483) U11.U23@8099.86,7463.92 ; U11.U23@8093.61,7463.92 ccw(c8078.51,7463.92) 8089.19,7474.59 ccw(c8099.86,7485.27) U11.U23@8099.86,7470.17
  BottomLayer w6: R74.3@7626,7602 7696,7602 7793,7505 8058.78,7505 v1(8080.78,7483) ; R74.3@7638.74,7597.76 cw(c7648.99,7587.51) 7648.99,7602 cw(c7648.99,7616.49) R74.3@7638.74,7606.24
NetR74_4: R74.4 U11.U24 | length 523.2
  TopLayer w6: v1(8041.41,7483) U11.U24@8060.49,7463.92 ; U11.U24@8054.24,7463.92 ccw(c8039.14,7463.92) 8049.82,7474.59 ccw(c8060.49,7485.27) U11.U24@8060.49,7470.17
  BottomLayer w6: R74.4@7626,7566 7701,7566 7784,7483 v1(8041.41,7483) ; R74.4@7638.74,7561.76 cw(c7648.99,7551.51) 7648.99,7566 cw(c7648.99,7580.49) R74.4@7638.74,7570.24
NetR78_1: R78.1 U11.B22 | length 336.2
  TopLayer w6: v1(8120,6854.14) U11.B22@8139.23,6873.37 ; U11.B22@8132.98,6873.37 cw(c8117.88,6873.37) 8128.56,6862.7 cw(c8139.23,6852.02) U11.B22@8139.23,6867.12
  BottomLayer w6: R78.1@8061.76,6626.74 ccw(c8051.51,6636.99) 8066,6636.99 ccw(c8080.49,6636.99) R78.1@8070.24,6626.74 ; R78.1@8066,6614 8066,6754 8120,6808 v1(8120,6854.14)
NetR78_2: R78.2 U11.C22 | length 393.6
  TopLayer w6: U11.C22@8139.23,6906.49 cw(c8139.23,6891.39) 8149.9,6902.07 cw(c8160.57,6912.74) U11.C22@8145.48,6912.74 ; U11.C22@8139.23,6912.74 v1(8158,6893.97)
  BottomLayer w6: R78.2@8097.76,6626.74 ccw(c8087.51,6636.99) 8102,6636.99 ccw(c8116.49,6636.99) R78.2@8106.24,6626.74 ; R78.2@8102,6614 8102,6648 8179,6725 8179,6872.97 v1(8158,6893.97)
NetR78_3: R78.3 U11.C21 | length 378.9
  TopLayer w6: U11.C21@8178.6,6906.49 cw(c8178.6,6891.39) 8189.27,6902.07 cw(c8199.94,6912.74) U11.C21@8184.85,6912.74 ; U11.C21@8178.6,6912.74 v1(8199,6892.34)
  BottomLayer w6: R78.3@8133.76,6626.74 ccw(c8123.51,6636.99) 8138,6636.99 ccw(c8152.49,6636.99) R78.3@8142.24,6626.74 ; R78.3@8138,6614 8138,6644 8199,6705 v1(8199,6892.34)
NetR78_4: R78.4 U11.D21 | length 419.1
  TopLayer w6: U11.D21@8178.6,6945.86 cw(c8178.6,6930.77) 8189.27,6941.44 cw(c8199.94,6952.11) U11.D21@8184.85,6952.11 ; U11.D21@8178.6,6952.11 v1(8198,6932.71)
  BottomLayer w6: R78.4@8169.76,6626.74 ccw(c8159.51,6636.99) 8174,6636.99 ccw(c8188.49,6636.99) R78.4@8178.24,6626.74 ; R78.4@8174,6614 8174,6644 8218,6688 8218,6912.71 v1(8198,6932.71)
NetR79_1: R79.1 U11.C20 | length 432.3
  TopLayer w6: U11.C20@8217.97,6906.49 cw(c8217.97,6891.39) 8228.64,6902.07 cw(c8239.31,6912.74) U11.C20@8224.22,6912.74 ; U11.C20@8217.97,6912.74 v1(8238,6892.71)
  BottomLayer w6: R79.1@8221.76,6626.74 ccw(c8182.54,6665.96) 8238,6665.96 ; R79.1@8226,6614 8238,6626 v1(8238,6892.71) ; R79.1@8226,6622.5 ccw(c8197.03,6651.47) 8238,6651.47 ; R79.1@8230.24,6618.26 ccw(c8211.51,6636.99) 8238,6636.99
NetR79_2: R79.2 U11.D20 | length 418.2
  TopLayer w6: U11.D20@8217.97,6945.86 cw(c8217.97,6930.77) 8228.64,6941.44 cw(c8239.31,6952.11) U11.D20@8224.22,6952.11 ; U11.D20@8217.97,6952.11 v1(8238,6932.08)
  BottomLayer w6: v1(8238,6932.08) 8257,6913.08 8257,6619 R79.2@8262,6614 ; 8257,6634.57 ccw(c8274.07,6634.57) R79.2@8262,6622.5 ; 8257,6649.06 ccw(c8288.56,6649.06) R79.2@8266.24,6626.74
NetR79_3: R79.3 U11.C19 | length 362
  TopLayer w6: U11.C19@8257.33,6906.49 cw(c8257.3,6891.39) 8267.99,6902.05 cw(c8278.68,6912.7) U11.C19@8263.59,6912.73 ; U11.C19@8257.34,6912.74 v1(8277,6893)
  BottomLayer w6: v1(8277,6893) 8277,6782 8298,6761 R79.3@8298,6614 ; R79.3@8293.76,6626.74 ccw(c8283.51,6636.99) 8298,6636.99 ccw(c8312.49,6636.99) R79.3@8302.24,6626.74
NetR79_4: R79.4 U11.D19 | length 416.3
  TopLayer w6: U11.D19@8257.34,6945.86 cw(c8257.34,6930.77) 8268.01,6941.44 cw(c8278.68,6952.11) U11.D19@8263.59,6952.11 ; U11.D19@8257.34,6952.11 v1(8277,6932.45)
  BottomLayer w6: v1(8277,6932.45) 8295,6914.45 8295,6798 8334,6759 R79.4@8334,6614 ; R79.4@8329.76,6626.74 ccw(c8319.51,6636.99) 8334,6636.99 ccw(c8348.49,6636.99) R79.4@8338.24,6626.74
NetR82_1: R82.1 U11.AE4 | length 398.7
  TopLayer w6: v1@8824.46,8077.93 cw(c8815.93,8069.39) 8828,8069.39 cw(c8840.07,8069.39) v1@8831.54,8077.93 ; v1(8828,8081.46) 8828,7798.77 U11.AE4@8847.89,7778.88 ; U11.AE4@8841.64,7778.88 ccw(c8826.54,7778.88) 8837.22,7789.56 ccw(c8847.89,7800.23) U11.AE4@8847.89,7785.13
  BottomLayer w6: v1(8828,8081.46) R82.1@8846.54,8100 ; R82.1@8828,8086.46 ccw(c8828,8098.54) 8836.54,8090 ccw(c8845.07,8081.46) R82.1@8833,8081.46
NetR92_2: R92.2 U1.180 | length 624.5
  TopLayer w10: R92.2@4705.46,7160 4876,7330.54 4876,7659 4890.29,7673.29 U1.180@4924.9,7673.29
NetR93_2: R93.2 U1.179 | length 552.5
  TopLayer w10: R93.2@4705.46,7260 4857,7411.54 4857,7674 4875.98,7692.98 U1.179@4924.9,7692.98
NetS2_2: S2.2 U8.3 | length 453
  TopLayer w12: U8.3@7221.09,7991.67 ccw(c7211.17,8001.59) 7225.2,8001.59 ccw(c7239.23,8001.59) U8.3@7229.31,7991.67 ; U8.3@7225.2,7960 v1(7225.2,8027.2)
  BottomLayer w12: v1(7225.2,8027.2) 7225.2,8157.87 S2.2@7390,8322.68
NSTATUS: R65.1 U1.146 | length 275.1
  TopLayer w12: U1.146@4937.69,8342.58 4990.42,8342.58 v3(5005,8328) ; v3@4999,8328 ccw(c4984.51,8328) 4994.76,8338.24 ccw(c5005,8348.49) v3@5005,8334
  BottomLayer w12: v3@5009.24,8323.76 cw(c5019.49,8313.51) 5019.49,8328 cw(c5019.49,8342.49) v3@5009.24,8332.24 ; 5032.83,8328 ccw(c5032.83,8369.96) R65.1@5063.34,8341.16 ; R65.1@5054.62,8349.39 cw(c5005,8396.22) v3(5005,8328) 5054.54,8328 R65.1@5066.54,8340
P\C\I\6\6\: R80.1 U11.AD1 | length 780.3
  TopLayer w6: v1@8943.46,7981.54 ccw(c8934.93,7990.07) 8947,7990.07 ccw(c8959.07,7990.07) v1@8950.54,7981.54 ; v1@8943.46,8162.93 cw(c8934.93,8154.39) 8947,8154.39 cw(c8959.07,8154.39) v1@8950.54,8162.93 ; v1(8947,7758.51) U11.AD1@8966,7739.51 ; v1(8947,7978) v1(8947,8166.46) ; U11.AD1@8959.75,7739.51 ccw(c8944.65,7739.51) 8955.33,7750.18 ccw(c8966,7760.86) U11.AD1@8966,7745.76
  BottomLayer w6: R80.1@8913.46,8200 v1(8947,8166.46) ; R80.1@8915.43,8183.31 cw(c8915.43,8147.79) 8940.56,8172.91 ; R80.1@8915.43,8189.31 cw(c8915.43,8168.27) R80.1@8930.31,8183.15 ; R80.1@8926.12,8200 ccw(c8956.67,8200) 8935.07,8178.4 ; R80.1@8932.12,8200 ccw(c8977.15,8200) v1@8945.31,8168.16 ; v1@8942,7978 cw(c8929.93,7978) 8938.46,7969.46 cw(c8947,7960.93) v1@8947,7973 ; v1@8942,8166.46 ccw(c8929.93,8166.46) 8938.46,8175 ccw(c8947,8183.54) v1@8947,8171.46 ; v1(8947,7758.51) 8905.49,7758.51 8861.99,7802.01 8861.99,7892.99 v1(8947,7978)
P_AD0: U11.Y3 U21.29 | length 354
  TopLayer w6: U11.Y3@8887.26,7582.03 v1(8908,7562) ; U11.Y3@8887.37,7575.78 cw(c8887.63,7560.69) 8898.12,7571.55 cw(c8908.6,7582.4) U11.Y3@8893.51,7582.14
  BottomLayer w6: v1(8908,7562) 9053.99,7562 9090,7525.98 U21.29@9185.04,7525.98 ; U21.29@9149.4,7524.21 ccw(c9145.12,7519.92) 9145.12,7525.99 ccw(c9145.12,7532.05) U21.29@9149.4,7527.76
P_AD1: U11.AA1 U21.35 | length 299.6
  TopLayer w6: U11.AA1@8966,7621.4 9008.4,7621.4 v1(9031.09,7644.1) ; U11.AA1@8970.42,7616.98 cw(c8981.09,7606.31) 8981.09,7621.4 cw(c8981.09,7636.5) U11.AA1@8970.42,7625.82 ; v1@9026.09,7644.1 cw(c9014.02,7644.1) 9022.56,7635.56 cw(c9031.09,7627.02) v1@9031.09,7639.1
  BottomLayer w6: v1(9031.09,7644.1) U21.35@9185.04,7644.1 ; v1@9034.63,7640.56 cw(c9043.17,7632.02) 9043.17,7644.1 cw(c9043.17,7656.17) v1@9034.63,7647.63 ; U21.35@9149.4,7642.32 ccw(c9145.12,7638.03) 9145.12,7644.1 ccw(c9145.12,7650.16) U21.35@9149.4,7645.87
P_AD2: U11.Y4 U21.28 | length 401.8
  TopLayer w6: U11.Y4@8847.89,7575.78 cw(c8847.89,7560.69) 8858.56,7571.36 cw(c8869.24,7582.03) U11.Y4@8854.14,7582.03 ; U11.Y4@8847.89,7582.03 v1(8867.92,7562)
  BottomLayer w6: v1(8867.92,7562) 8885.92,7544 9046,7544 9083.7,7506.3 U21.28@9185.04,7506.3 ; U21.28@9149.4,7504.52 ccw(c9145.12,7500.24) 9145.12,7506.3 ccw(c9145.12,7512.36) U21.28@9149.4,7508.08
P_AD3: U11.Y2 U21.34 | length 347.1
  TopLayer w6: U11.Y2@8926.63,7582.03 8945.6,7601 9037,7601 v1(9060.41,7624.41) ; U11.Y2@8926.63,7588.28 ccw(c8926.63,7603.38) 8937.3,7592.7 ccw(c8947.98,7582.03) U11.Y2@8932.88,7582.03 ; v1@9055.41,7624.41 cw(c9043.34,7624.41) 9051.87,7615.87 cw(c9060.41,7607.34) v1@9060.41,7619.41
  BottomLayer w6: v1(9060.41,7624.41) U21.34@9185.04,7624.41 ; v1@9063.95,7620.87 cw(c9072.48,7612.34) 9072.48,7624.41 cw(c9072.48,7636.48) v1@9063.95,7627.95 ; U21.34@9149.4,7622.63 ccw(c9145.12,7618.35) 9145.12,7624.41 ccw(c9145.12,7630.47) U21.34@9149.4,7626.19
P_AD4: U11.W3 U21.27 | length 354.2
  TopLayer w6: U11.W3@8887.26,7536.41 cw(c8887.26,7521.32) 8897.93,7531.99 cw(c8908.61,7542.66) U11.W3@8893.51,7542.66 ; U11.W3@8887.26,7542.66 v1(8905.92,7524)
  BottomLayer w6: v1(8905.92,7524) 9039,7524 9076.39,7486.61 U21.27@9185.04,7486.61 ; U21.27@9149.4,7484.84 ccw(c9145.12,7480.55) 9145.12,7486.62 ccw(c9145.12,7492.68) U21.27@9149.4,7488.39
P_AD5: U11.Y1 U21.33 | length 299.6
  TopLayer w6: U11.Y1@8966,7582.03 9047.03,7582.03 9069.73,7604.73 v1(9128.73,7604.73) ; U11.Y1@8970.42,7577.61 cw(c8981.09,7566.94) 8981.09,7582.03 cw(c8981.09,7597.13) U11.Y1@8970.42,7586.45 ; v1@9125.19,7601.19 ccw(c9116.65,7592.65) 9116.65,7604.73 ccw(c9116.65,7616.8) v1@9125.19,7608.26
  BottomLayer w6: v1(9128.73,7604.73) U21.33@9185.04,7604.73 ; v1@9132.26,7601.19 cw(c9140.8,7592.65) 9140.8,7604.73 cw(c9140.8,7616.8) v1@9132.26,7608.26 ; U21.33@9149.4,7602.95 ccw(c9145.12,7598.66) 9145.12,7604.73 ccw(c9145.12,7610.79) U21.33@9149.4,7606.5
P_AD6: U11.W4 U21.26 | length 401.8
  TopLayer w6: U11.W4@8847.89,7536.41 cw(c8847.89,7521.32) 8858.56,7531.99 cw(c8869.24,7542.66) U11.W4@8854.14,7542.66 ; U11.W4@8847.89,7542.66 v1(8866.55,7524)
  BottomLayer w6: v1(8866.55,7524) 8886.55,7504 9032,7504 9069.07,7466.93 U21.26@9185.04,7466.93 ; U21.26@9149.4,7465.15 ccw(c9145.12,7460.87) 9145.12,7466.93 ccw(c9145.12,7472.99) U21.26@9149.4,7468.71
P_AD7: U11.W2 U21.31 | length 359.4
  TopLayer w6: U11.W2@8926.63,7542.66 8946.97,7563 9057,7563 v1(9080,7586) ; U11.W2@8926.63,7548.91 ccw(c8926.63,7564.01) 8937.3,7553.33 ccw(c8947.98,7542.66) U11.W2@8932.88,7542.66 ; v1@9075,7586 cw(c9062.93,7586) 9071.46,7577.46 cw(c9080,7568.93) v1@9080,7581
  BottomLayer w6: v1(9080,7586) 9100,7586 9120.65,7565.35 U21.31@9185.04,7565.35 U21.31@9182.68,7563 ; v1@9083.54,7582.46 cw(c9092.07,7573.93) 9092.07,7586 cw(c9092.07,7598.07) v1@9083.54,7589.54 ; U21.31@9149.4,7563.58 ccw(c9145.12,7559.29) 9145.12,7565.36 ccw(c9145.12,7571.42) U21.31@9149.4,7567.13
P_AD8: U11.V2 U21.30 | length 347.1
  TopLayer w6: U11.V2@8926.63,7503.29 8947.34,7524 9109,7524 v1(9130.67,7545.67) ; U11.V2@8926.63,7509.54 ccw(c8926.63,7524.64) 8937.3,7513.96 ccw(c8947.98,7503.29) U11.V2@8932.88,7503.29 ; v1@9125.67,7545.67 cw(c9113.6,7545.67) 9122.13,7537.13 cw(c9130.67,7528.6) v1@9130.67,7540.67
  BottomLayer w6: v1(9130.67,7545.67) U21.30@9185.04,7545.67 ; v1@9134.21,7542.13 cw(c9142.74,7533.6) 9142.74,7545.67 cw(c9142.74,7557.74) v1@9134.21,7549.21 ; U21.30@9149.4,7543.89 ccw(c9145.12,7539.61) 9145.12,7545.67 ccw(c9145.12,7551.73) U21.30@9149.4,7547.45
P_AD9: U11.V3 U21.25 | length 354.2
  TopLayer w6: U11.V3@8887.26,7497.04 cw(c8887.26,7481.95) 8897.93,7492.62 cw(c8908.61,7503.29) U11.V3@8893.51,7503.29 ; U11.V3@8887.26,7503.29 v1(8906.55,7484)
  BottomLayer w6: v1(8906.55,7484) 9032,7484 9068.75,7447.24 U21.25@9185.04,7447.24 ; U21.25@9149.4,7445.47 ccw(c9145.12,7441.18) 9145.12,7447.24 ccw(c9145.12,7453.31) U21.25@9149.4,7449.02
P_AD10: U11.V1 U16.25 | length 306.3
  TopLayer w6: U11.V1@8966,7503.29 9010.71,7503.29 9141.25,7372.76 U16.25@9185.04,7372.76 ; U11.V1@8970.42,7498.87 cw(c8981.09,7488.2) 8981.09,7503.29 cw(c8981.09,7518.39) U11.V1@8970.42,7507.71 ; U16.25@9149.4,7370.98 ccw(c9145.12,7366.69) 9145.12,7372.76 ccw(c9145.12,7378.82) U16.25@9149.4,7374.53
P_AD11: U11.U4 U20.44 | length 429.5
  TopLayer w6: U11.U4@8847.89,7457.67 cw(c8847.89,7442.58) 8858.56,7453.25 cw(c8869.24,7463.92) U11.U4@8854.14,7463.92 ; U11.U4@8847.89,7463.92 v1(8867.81,7444)
  BottomLayer w6: v1(8867.81,7444) 8885.81,7426 8960,7426 8981,7405 9029,7405 9112.74,7321.26 U20.44@9185.04,7321.26 ; U20.44@9149.4,7319.48 ccw(c9145.12,7315.2) 9145.12,7321.26 ccw(c9145.12,7327.32) U20.44@9149.4,7323.04
P_AD12: U11.U2 U16.26 | length 354.2
  TopLayer w6: U11.U2@8926.63,7463.92 8946.71,7484 9006,7484 9136.93,7353.07 U16.26@9185.04,7353.07 ; U11.U2@8926.63,7470.17 ccw(c8926.63,7485.27) 8937.3,7474.59 ccw(c8947.98,7463.92) U11.U2@8932.88,7463.92 ; U16.26@9149.4,7351.29 ccw(c9145.12,7347.01) 9145.12,7353.07 ccw(c9145.12,7359.13) U16.26@9149.4,7354.85
P_AD13: U11.U3 U20.45 | length 382
  TopLayer w6: U11.U3@8887.26,7457.67 cw(c8887.26,7442.58) 8897.93,7453.25 cw(c8908.61,7463.92) U11.U3@8893.51,7463.92 ; U11.U3@8887.26,7463.92 v1(8907.18,7444)
  BottomLayer w6: v1(8907.18,7444) 9018,7444 9121.06,7340.94 U20.45@9185.04,7340.94 ; U20.45@9149.4,7339.17 ccw(c9145.12,7334.88) 9145.12,7340.95 ccw(c9145.12,7347.01) U20.45@9149.4,7342.72
P_AD14: U11.U1 U16.27 | length 306.3
  TopLayer w6: U11.U1@8966,7463.92 9003.08,7463.92 9133.61,7333.39 U16.27@9185.04,7333.39 ; U11.U1@8970.42,7459.5 cw(c8981.09,7448.83) 8981.09,7463.92 cw(c8981.09,7479.02) U11.U1@8970.42,7468.34 ; U16.27@9149.4,7331.61 ccw(c9145.12,7327.32) 9145.12,7333.39 ccw(c9145.12,7339.45) U16.27@9149.4,7335.16
P_AD15: U11.T3 U20.43 | length 382
  TopLayer w6: U11.T3@8887.26,7418.3 cw(c8887.26,7403.21) 8897.93,7413.88 cw(c8908.61,7424.55) U11.T3@8893.51,7424.55 ; U11.T3@8887.26,7424.55 v1(8905.81,7406)
  BottomLayer w6: v1(8905.81,7406) 8958,7406 8977.45,7386.55 9025.45,7386.55 9110.42,7301.57 U20.43@9185.04,7301.57 ; U20.43@9149.4,7299.8 ccw(c9145.12,7295.51) 9145.12,7301.58 ccw(c9145.12,7307.64) U20.43@9149.4,7303.35
P_AD16: U11.M3 U20.37 | length 385.5
  TopLayer w6: U11.M3@8887.26,7260.82 cw(c8887.26,7245.73) 8897.93,7256.4 cw(c8908.61,7267.07) U11.M3@8893.51,7267.07 ; U11.M3@8887.26,7267.07 v1(8907.33,7247)
  BottomLayer w6: v1(8907.33,7247) 8972,7247 8996,7271 9012,7271 9099.53,7183.47 U20.37@9185.04,7183.47 ; U20.37@9149.4,7181.69 ccw(c9145.12,7177.4) 9145.12,7183.47 ccw(c9145.12,7189.53) U20.37@9149.4,7185.24
P_AD17: U11.M2 U16.34 | length 337.8
  TopLayer w6: U11.M2@8926.63,7267.07 8946.56,7287 9042,7287 9133.41,7195.59 U16.34@9185.04,7195.59 ; U11.M2@8926.63,7273.32 ccw(c8926.63,7288.42) 8937.3,7277.74 ccw(c8947.98,7267.07) U11.M2@8932.88,7267.07 ; U16.34@9149.4,7193.81 ccw(c9145.12,7189.53) 9145.12,7195.59 ccw(c9145.12,7201.65) U16.34@9149.4,7197.37
P_AD18: U11.M4 U20.36 | length 428.9
  TopLayer w6: U11.M4@8847.89,7260.82 cw(c8847.89,7245.73) 8858.56,7256.4 cw(c8869.24,7267.07) U11.M4@8854.14,7267.07 ; U11.M4@8847.89,7267.07 v1(8867.96,7247)
  BottomLayer w6: v1(8867.96,7247) 8885.96,7229 8974,7229 8993,7248 9014,7248 9098.22,7163.78 U20.36@9185.04,7163.78 ; U20.36@9149.4,7162 ccw(c9145.12,7157.72) 9145.12,7163.78 ccw(c9145.12,7169.84) U20.36@9149.4,7165.56
P_AD19: U11.L2 U16.36 | length 337.2
  TopLayer w6: U11.L2@8926.63,7227.7 8945.93,7247 9033,7247 9123.78,7156.22 U16.36@9185.04,7156.22 ; U11.L2@8926.63,7233.95 ccw(c8926.63,7249.05) 8937.3,7238.37 ccw(c8947.98,7227.7) U11.L2@8932.88,7227.7 ; U16.36@9149.4,7154.44 ccw(c9145.12,7150.16) 9145.12,7156.22 ccw(c9145.12,7162.28) U16.36@9149.4,7158
P_AD20: U11.L3 U20.35 | length 365.6
  TopLayer w6: U11.L3@8887.26,7221.45 cw(c8887.26,7206.36) 8897.93,7217.03 cw(c8908.61,7227.7) U11.L3@8893.51,7227.7 ; U11.L3@8887.26,7227.7 v1(8905.96,7209)
  BottomLayer w6: v1(8905.96,7209) 9030,7209 9094.91,7144.1 U20.35@9185.04,7144.1 ; U20.35@9149.4,7142.32 ccw(c9145.12,7138.03) 9145.12,7144.1 ccw(c9145.12,7150.16) U20.35@9149.4,7145.87
P_AD21: U11.K2 U16.37 | length 330.2
  TopLayer w6: U11.K2@8926.63,7188.33 8947.3,7209 9045,7209 9117.47,7136.53 U16.37@9185.04,7136.53 ; U11.K2@8926.63,7194.58 ccw(c8926.63,7209.68) 8937.3,7199 ccw(c8947.98,7188.33) U11.K2@8932.88,7188.33 ; U16.37@9149.4,7134.76 ccw(c9145.12,7130.47) 9145.12,7136.53 ccw(c9145.12,7142.6) U16.37@9149.4,7138.31
P_AD22: U11.L4 U20.34 | length 413.2
  TopLayer w6: U11.L4@8847.89,7221.45 cw(c8847.89,7206.36) 8858.56,7217.03 cw(c8869.24,7227.7) U11.L4@8854.14,7227.7 ; U11.L4@8847.89,7227.7 v1(8866.59,7209)
  BottomLayer w6: v1(8866.59,7209) 8886.59,7189 9025,7189 9089.59,7124.41 U20.34@9185.04,7124.41 ; U20.34@9149.4,7122.63 ccw(c9145.12,7118.35) 9145.12,7124.41 ccw(c9145.12,7130.47) U20.34@9149.4,7126.19
P_AD23: U11.K1 U16.38 | length 281.9
  TopLayer w6: U11.K1@8966,7188.33 9040.67,7188.33 9112.15,7116.85 U16.38@9185.04,7116.85 ; U11.K1@8970.42,7183.91 cw(c8981.09,7173.24) 8981.09,7188.33 cw(c8981.09,7203.42) U11.K1@8970.42,7192.75 ; U16.38@9149.4,7115.07 ccw(c9145.12,7110.79) 9145.12,7116.85 ccw(c9145.12,7122.91) U16.38@9149.4,7118.63
P_AD24: U11.K4 U20.31 | length 421.3
  TopLayer w6: U11.K4@8847.89,7182.08 cw(c8847.89,7166.99) 8858.56,7177.66 cw(c8869.24,7188.33) U11.K4@8854.14,7188.33 ; U11.K4@8847.89,7188.33 v1(8867.22,7169)
  BottomLayer w6: v1(8867.22,7169) 8887.22,7149 9021,7149 9104.65,7065.35 U20.31@9185.04,7065.35 ; U20.31@9149.4,7063.58 ccw(c9145.12,7059.29) 9145.12,7065.36 ccw(c9145.12,7071.42) U20.31@9149.4,7067.13
P_AD25: U11.J1 U16.40 | length 281.9
  TopLayer w6: U11.J1@8966,7148.96 9026.04,7148.96 9097.52,7077.48 U16.40@9185.04,7077.48 ; U11.J1@8970.42,7144.54 cw(c8981.09,7133.87) 8981.09,7148.96 cw(c8981.09,7164.05) U11.J1@8970.42,7153.38 ; U16.40@9149.4,7075.7 ccw(c9145.12,7071.42) 9145.12,7077.48 ccw(c9145.12,7083.54) U16.40@9149.4,7079.26
P_AD26: U11.J3 U20.30 | length 373.8
  TopLayer w6: U11.J3@8887.26,7142.71 cw(c8887.26,7127.62) 8897.93,7138.29 cw(c8908.61,7148.96) U11.J3@8893.51,7148.96 ; U11.J3@8887.26,7148.96 v1(8907.22,7129)
  BottomLayer w6: v1(8907.22,7129) 9017,7129 9100.33,7045.67 U20.30@9185.04,7045.67 ; U20.30@9149.4,7043.89 ccw(c9145.12,7039.61) 9145.12,7045.67 ccw(c9145.12,7051.73) U20.30@9149.4,7047.45
P_AD27: U11.H2 U16.42 | length 337.3
  TopLayer w6: U11.H2@8926.63,7109.59 8946.04,7129 9023,7129 9113.89,7038.11 U16.42@9185.04,7038.11 ; U11.H2@8926.63,7115.84 ccw(c8926.63,7130.94) 8937.3,7120.26 ccw(c8947.98,7109.59) U11.H2@8932.88,7109.59 ; U16.42@9149.4,7036.33 ccw(c9145.12,7032.05) 9145.12,7038.11 ccw(c9145.12,7044.17) U16.42@9149.4,7039.89
P_AD28: U11.J4 U20.29 | length 421.3
  TopLayer w6: U11.J4@8847.89,7142.71 cw(c8847.89,7127.62) 8858.56,7138.29 cw(c8869.24,7148.96) U11.J4@8854.14,7148.96 ; U11.J4@8847.89,7148.96 v1(8867.85,7129)
  BottomLayer w6: v1(8867.85,7129) 8885.85,7111 8976,7111 9061.01,7025.98 U20.29@9185.04,7025.98 ; U20.29@9149.4,7024.21 ccw(c9145.12,7019.92) 9145.12,7025.99 ccw(c9145.12,7032.05) U20.29@9149.4,7027.76
P_AD29: U11.G2 U16.43 | length 330.3
  TopLayer w6: U11.G2@8926.63,7070.22 8947.41,7091 9035,7091 9107.58,7018.43 U16.43@9185.04,7018.43 ; U11.G2@8926.63,7076.47 ccw(c8926.63,7091.57) 8937.3,7080.89 ccw(c8947.98,7070.22) U11.G2@8932.88,7070.22 ; U16.43@9149.4,7016.65 ccw(c9145.12,7012.36) 9145.12,7018.43 ccw(c9145.12,7024.49) U16.43@9149.4,7020.2
P_AD30: U11.H3 U20.28 | length 373.8
  TopLayer w6: U11.H3@8887.26,7103.34 cw(c8887.26,7088.25) 8897.93,7098.92 cw(c8908.61,7109.59) U11.H3@8893.51,7109.59 ; U11.H3@8887.26,7109.59 v1(8905.85,7091)
  BottomLayer w6: v1(8905.85,7091) 8976,7091 9060.7,7006.3 U20.28@9185.04,7006.3 ; U20.28@9149.4,7004.52 ccw(c9145.12,7000.24) 9145.12,7006.3 ccw(c9145.12,7012.36) U20.28@9149.4,7008.08
P_AD31: U11.G1 U16.44 | length 281.9
  TopLayer w6: U11.G1@8966,7070.22 9030.78,7070.22 9102.26,6998.74 U16.44@9185.04,6998.74 ; U11.G1@8970.42,7065.8 cw(c8981.09,7055.13) 8981.09,7070.22 cw(c8981.09,7085.31) U11.G1@8970.42,7074.64 ; U16.44@9149.4,6996.96 ccw(c9145.12,6992.68) 9145.12,6998.74 ccw(c9145.12,7004.8) U16.44@9149.4,7000.52
P_CBE0: U11.V4 U20.46 | length 429.5
  TopLayer w6: U11.V4@8847.89,7497.04 cw(c8847.89,7481.95) 8858.56,7492.62 cw(c8869.24,7503.29) U11.V4@8854.14,7503.29 ; U11.V4@8847.89,7503.29 v1(8867.18,7484)
  BottomLayer w6: v1(8867.18,7484) 8887.18,7464 9027,7464 9130.37,7360.63 U20.46@9185.04,7360.63 ; U20.46@9149.4,7358.85 ccw(c9145.12,7354.57) 9145.12,7360.63 ccw(c9145.12,7366.69) U20.46@9149.4,7362.41
P_CBE1: U11.T2 U16.28 | length 353.7
  TopLayer w6: U11.T2@8926.63,7424.55 8946.08,7444 9001,7444 9131.3,7313.7 U16.28@9185.04,7313.7 ; U11.T2@8926.63,7430.8 ccw(c8926.63,7445.9) 8937.3,7435.22 ccw(c8947.98,7424.55) U11.T2@8932.88,7424.55 ; U16.28@9149.4,7311.92 ccw(c9145.12,7307.64) 9145.12,7313.7 ccw(c9145.12,7319.76) U16.28@9149.4,7315.48
P_CBE2: U11.M1 U16.35 | length 290
  TopLayer w6: U11.M1@8966,7267.07 9035.93,7267.07 9127.09,7175.9 U16.35@9185.04,7175.9 ; U11.M1@8970.42,7262.65 cw(c8981.09,7251.98) 8981.09,7267.07 cw(c8981.09,7282.16) U11.M1@8970.42,7271.49 ; U16.35@9149.4,7174.13 ccw(c9145.12,7169.84) 9145.12,7175.91 ccw(c9145.12,7181.97) U16.35@9149.4,7177.68
P_CBE3: U11.J2 U16.39 | length 329.7
  TopLayer w6: U11.J2@8926.63,7148.96 8946.67,7169 9035,7169 9106.83,7097.16 U16.39@9185.04,7097.16 ; U11.J2@8926.63,7155.21 ccw(c8926.63,7170.31) 8937.3,7159.63 ccw(c8947.98,7148.96) U11.J2@8932.88,7148.96 ; U16.39@9149.4,7095.39 ccw(c9145.12,7091.1) 9145.12,7097.16 ccw(c9145.12,7103.23) U16.39@9149.4,7098.94
P_CLK: U11.C1 U16.46 | length 829.7
  TopLayer w6: U11.C1@8966,6912.74 9039.26,6912.74 9062,6890 9062,6802 9066,6798 9073,6798 9078,6803 9078,6961 9084,6967 9090,6967 9095,6962 9095,6803 9101,6797 9109,6797 9113,6801 9113,6946 9126.37,6959.37 U16.46@9185.04,6959.37 ; U11.C1@8970.42,6908.32 cw(c8981.09,6897.65) 8981.09,6912.74 cw(c8981.09,6927.83) U11.C1@8970.42,6917.16 ; U16.46@9149.4,6957.59 ccw(c9145.12,6953.31) 9145.12,6959.37 ccw(c9145.12,6965.43) U16.46@9149.4,6961.15
P_DEVSEL: U11.P1 U16.31 | length 290
  TopLayer w6: U11.P1@8966,7345.81 9028.19,7345.81 9119.35,7254.65 U16.31@9185.04,7254.65 ; U11.P1@8970.42,7341.39 cw(c8981.09,7330.72) 8981.09,7345.81 cw(c8981.09,7360.9) U11.P1@8970.42,7350.23 ; U16.31@9149.4,7252.87 ccw(c9145.12,7248.58) 9145.12,7254.65 ccw(c9145.12,7260.71) U16.31@9149.4,7256.42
